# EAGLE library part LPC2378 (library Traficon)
LPC2378 Single-chip 16-bit/32-bit microcontrollers; 512 kB flash with ISP/IAP, Ethernet, USB 2.0, CAN, 10-bit ADC/DAC
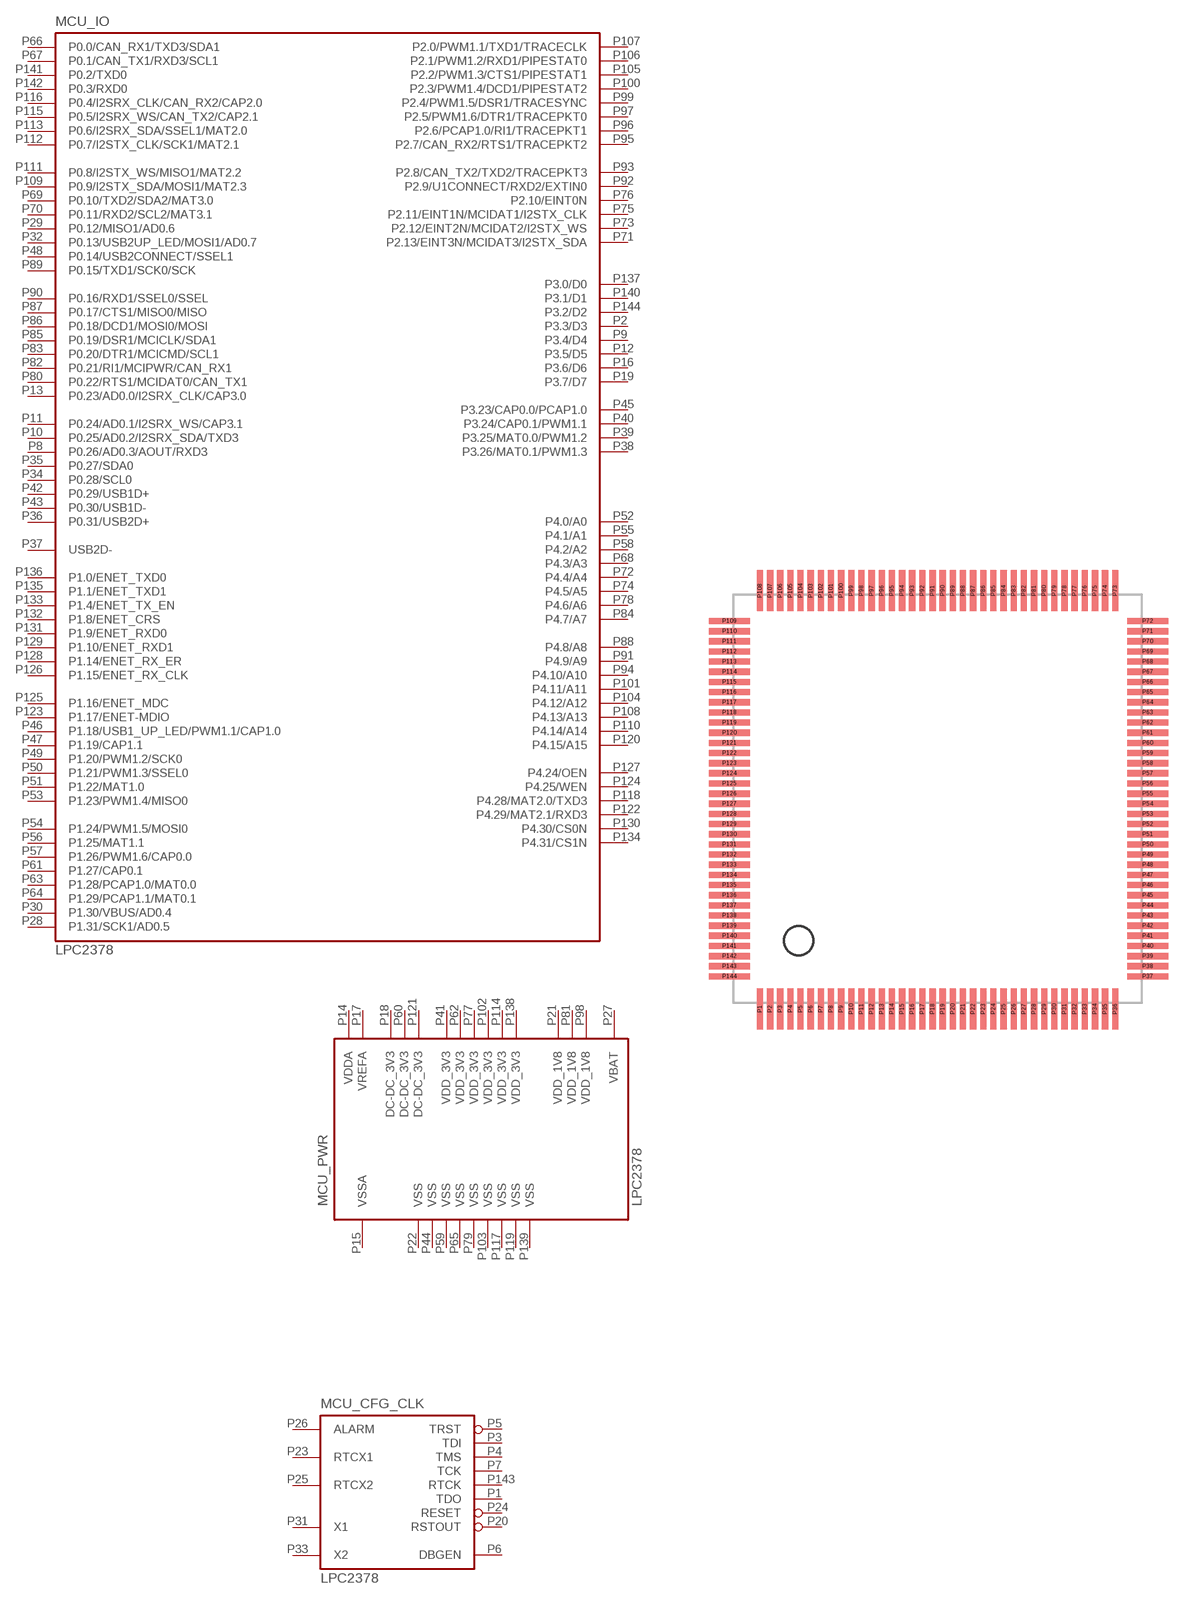
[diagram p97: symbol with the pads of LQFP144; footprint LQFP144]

Designator prefix MCU; gates _IO=LPC2378_IO _CFG_CLK=LPC_2378_MISC _PWR=LPC2378_POWER

## LPC2378FPD144  [LQFP144]
P1  _CFG_CLK:TDO
P2  _IO:P3.3/D3
P3  _CFG_CLK:TDI
P4  _CFG_CLK:TMS
P5  _CFG_CLK:TRST
P6  _CFG_CLK:DBGEN
P7  _CFG_CLK:TCK
P8  _IO:P0.26/AD0.3/AOUT/RXD3
P9  _IO:P3.4/D4
P10  _IO:P0.25/AD0.2/I2SRX_SDA/TXD3
P11  _IO:P0.24/AD0.1/I2SRX_WS/CAP3.1
P12  _IO:P3.5/D5
P13  _IO:P0.23/AD0.0/I2SRX_CLK/CAP3.0
P14  _PWR:VDDA  pwr
P15  _PWR:VSSA  pwr
P16  _IO:P3.6/D6
P17  _PWR:VREFA  pwr
P18  _PWR:DC-DC_3V3  pas
P19  _IO:P3.7/D7
P20  _CFG_CLK:RSTOUT
P21  _PWR:VDD_1V8  pwr
P22  _PWR:VSS  pwr
P23  _CFG_CLK:RTCX1
P24  _CFG_CLK:RESET
P25  _CFG_CLK:RTCX2
P26  _CFG_CLK:ALARM
P27  _PWR:VBAT  pwr
P28  _IO:P1.31/SCK1/AD0.5
P29  _IO:P0.12/MISO1/AD0.6
P30  _IO:P1.30/VBUS/AD0.4
P31  _CFG_CLK:X1
P32  _IO:P0.13/USB2UP_LED/MOSI1/AD0.7
P33  _CFG_CLK:X2
P34  _IO:P0.28/SCL0
P35  _IO:P0.27/SDA0
P36  _IO:P0.31/USB2D+
P37  _IO:USB2D-
P38  _IO:P3.26/MAT0.1/PWM1.3
P39  _IO:P3.25/MAT0.0/PWM1.2
P40  _IO:P3.24/CAP0.1/PWM1.1
P41  _PWR:VDD_3V3  pwr
P42  _IO:P0.29/USB1D+
P43  _IO:P0.30/USB1D-
P44  _PWR:VSS  pwr
P45  _IO:P3.23/CAP0.0/PCAP1.0
P46  _IO:P1.18/USB1_UP_LED/PWM1.1/CAP1.0
P47  _IO:P1.19/CAP1.1
P48  _IO:P0.14/USB2CONNECT/SSEL1
P49  _IO:P1.20/PWM1.2/SCK0
P50  _IO:P1.21/PWM1.3/SSEL0
P51  _IO:P1.22/MAT1.0
P52  _IO:P4.0/A0
P53  _IO:P1.23/PWM1.4/MISO0
P54  _IO:P1.24/PWM1.5/MOSI0
P55  _IO:P4.1/A1
P56  _IO:P1.25/MAT1.1
P57  _IO:P1.26/PWM1.6/CAP0.0
P58  _IO:P4.2/A2
P59  _PWR:VSS  pwr
P60  _PWR:DC-DC_3V3  pas
P61  _IO:P1.27/CAP0.1
P62  _PWR:VDD_3V3  pwr
P63  _IO:P1.28/PCAP1.0/MAT0.0
P64  _IO:P1.29/PCAP1.1/MAT0.1
P65  _PWR:VSS  pwr
P66  _IO:P0.0/CAN_RX1/TXD3/SDA1
P67  _IO:P0.1/CAN_TX1/RXD3/SCL1
P68  _IO:P4.3/A3
P69  _IO:P0.10/TXD2/SDA2/MAT3.0
P70  _IO:P0.11/RXD2/SCL2/MAT3.1
P71  _IO:P2.13/EINT3N/MCIDAT3/I2STX_SDA
P72  _IO:P4.4/A4
P73  _IO:P2.12/EINT2N/MCIDAT2/I2STX_WS
P74  _IO:P4.5/A5
P75  _IO:P2.11/EINT1N/MCIDAT1/I2STX_CLK
P76  _IO:P2.10/EINT0N
P77  _PWR:VDD_3V3  pwr
P78  _IO:P4.6/A6
P79  _PWR:VSS  pwr
P80  _IO:P0.22/RTS1/MCIDAT0/CAN_TX1
P81  _PWR:VDD_1V8  pwr
P82  _IO:P0.21/RI1/MCIPWR/CAN_RX1
P83  _IO:P0.20/DTR1/MCICMD/SCL1
P84  _IO:P4.7/A7
P85  _IO:P0.19/DSR1/MCICLK/SDA1
P86  _IO:P0.18/DCD1/MOSI0/MOSI
P87  _IO:P0.17/CTS1/MISO0/MISO
P88  _IO:P4.8/A8
P89  _IO:P0.15/TXD1/SCK0/SCK
P90  _IO:P0.16/RXD1/SSEL0/SSEL
P91  _IO:P4.9/A9
P92  _IO:P2.9/U1CONNECT/RXD2/EXTIN0
P93  _IO:P2.8/CAN_TX2/TXD2/TRACEPKT3
P94  _IO:P4.10/A10
P95  _IO:P2.7/CAN_RX2/RTS1/TRACEPKT2
P96  _IO:P2.6/PCAP1.0/RI1/TRACEPKT1
P97  _IO:P2.5/PWM1.6/DTR1/TRACEPKT0
P98  _PWR:VDD_1V8  pwr
P99  _IO:P2.4/PWM1.5/DSR1/TRACESYNC
P100  _IO:P2.3/PWM1.4/DCD1/PIPESTAT2
P101  _IO:P4.11/A11
P102  _PWR:VDD_3V3  pwr
P103  _PWR:VSS  pwr
P104  _IO:P4.12/A12
P105  _IO:P2.2/PWM1.3/CTS1/PIPESTAT1
P106  _IO:P2.1/PWM1.2/RXD1/PIPESTAT0
P107  _IO:P2.0/PWM1.1/TXD1/TRACECLK
P108  _IO:P4.13/A13
P109  _IO:P0.9/I2STX_SDA/MOSI1/MAT2.3
P110  _IO:P4.14/A14
P111  _IO:P0.8/I2STX_WS/MISO1/MAT2.2
P112  _IO:P0.7/I2STX_CLK/SCK1/MAT2.1
P113  _IO:P0.6/I2SRX_SDA/SSEL1/MAT2.0
P114  _PWR:VDD_3V3  pwr
P115  _IO:P0.5/I2SRX_WS/CAN_TX2/CAP2.1
P116  _IO:P0.4/I2SRX_CLK/CAN_RX2/CAP2.0
P117  _PWR:VSS  pwr
P118  _IO:P4.28/MAT2.0/TXD3
P119  _PWR:VSS  pwr
P120  _IO:P4.15/A15
P121  _PWR:DC-DC_3V3  pas
P122  _IO:P4.29/MAT2.1/RXD3
P123  _IO:P1.17/ENET-MDIO
P124  _IO:P4.25/WEN
P125  _IO:P1.16/ENET_MDC
P126  _IO:P1.15/ENET_RX_CLK
P127  _IO:P4.24/OEN
P128  _IO:P1.14/ENET_RX_ER
P129  _IO:P1.10/ENET_RXD1
P130  _IO:P4.30/CS0N
P131  _IO:P1.9/ENET_RXD0
P132  _IO:P1.8/ENET_CRS
P133  _IO:P1.4/ENET_TX_EN
P134  _IO:P4.31/CS1N
P135  _IO:P1.1/ENET_TXD1
P136  _IO:P1.0/ENET_TXD0
P137  _IO:P3.0/D0
P138  _PWR:VDD_3V3  pwr
P139  _PWR:VSS  pwr
P140  _IO:P3.1/D1
P141  _IO:P0.2/TXD0
P142  _IO:P0.3/RXD0
P143  _CFG_CLK:RTCK
P144  _IO:P3.2/D2

## Footprint LQFP144 (pad centres in mm)
smd 0.305 x 2: P1 -8.89,-10.34; P2 -8.39,-10.34; P3 -7.89,-10.34; P4 -7.39,-10.34; P5 -6.89,-10.34; P6 -6.39,-10.34; P7 -5.89,-10.34; P8 -5.39,-10.34; P9 -4.89,-10.34; P10 -4.39,-10.34; P11 -3.89,-10.34; P12 -3.39,-10.34; P13 -2.89,-10.34; P14 -2.39,-10.34; P15 -1.89,-10.34; P16 -1.39,-10.34; P17 -0.89,-10.34; P18 -0.39,-10.34; P19 0.11,-10.34; P20 0.61,-10.34; P21 1.11,-10.34; P22 1.61,-10.34; P23 2.11,-10.34; P24 2.61,-10.34; P25 3.11,-10.34; P26 3.61,-10.34; P27 4.11,-10.34; P28 4.61,-10.34; P29 5.11,-10.34; P30 5.61,-10.34; P31 6.11,-10.34; P32 6.61,-10.34; P33 7.11,-10.34; P34 7.61,-10.34; P35 8.11,-10.34; P36 8.61,-10.34; P73 8.61,10.26; P74 8.11,10.26; P75 7.61,10.26; P76 7.11,10.26; P77 6.61,10.26; P78 6.11,10.26; P79 5.61,10.26; P80 5.11,10.26; P81 4.61,10.26; P82 4.11,10.26; P83 3.61,10.26; P84 3.11,10.26; P85 2.61,10.26; P86 2.11,10.26; P87 1.61,10.26; P88 1.11,10.26; P89 0.61,10.26; P90 0.11,10.26; P91 -0.39,10.26; P92 -0.89,10.26; P93 -1.39,10.26; P94 -1.89,10.26; P95 -2.39,10.26; P96 -2.89,10.26; P97 -3.39,10.26; P98 -3.89,10.26; P99 -4.39,10.26; P100 -4.89,10.26; P101 -5.39,10.26; P102 -5.89,10.26; P103 -6.39,10.26; P104 -6.89,10.26; P105 -7.39,10.26; P106 -7.89,10.26; P107 -8.39,10.26; P108 -8.89,10.26
smd 2 x 0.305: P37 10.21,-8.74; P38 10.21,-8.24; P39 10.21,-7.74; P40 10.21,-7.24; P41 10.21,-6.74; P42 10.21,-6.24; P43 10.21,-5.74; P44 10.21,-5.24; P45 10.21,-4.74; P46 10.21,-4.24; P47 10.21,-3.74; P48 10.21,-3.24; P49 10.21,-2.74; P50 10.21,-2.24; P51 10.21,-1.74; P52 10.21,-1.24; P53 10.21,-0.74; P54 10.21,-0.24; P55 10.21,0.26; P56 10.21,0.76; P57 10.21,1.26; P58 10.21,1.76; P59 10.21,2.26; P60 10.21,2.76; P61 10.21,3.26; P62 10.21,3.76; P63 10.21,4.26; P64 10.21,4.76; P65 10.21,5.26; P66 10.21,5.76; P67 10.21,6.26; P68 10.21,6.76; P69 10.21,7.26; P70 10.21,7.76; P71 10.21,8.26; P72 10.21,8.76; P109 -10.39,8.76; P110 -10.39,8.26; P111 -10.39,7.76; P112 -10.39,7.26; P113 -10.39,6.76; P114 -10.39,6.26; P115 -10.39,5.76; P116 -10.39,5.26; P117 -10.39,4.76; P118 -10.39,4.26; P119 -10.39,3.76; P120 -10.39,3.26; P121 -10.39,2.76; P122 -10.39,2.26; P123 -10.39,1.76; P124 -10.39,1.26; P125 -10.39,0.76; P126 -10.39,0.26; P127 -10.39,-0.24; P128 -10.39,-0.74; P129 -10.39,-1.24; P130 -10.39,-1.74; P131 -10.39,-2.24; P132 -10.39,-2.74; P133 -10.39,-3.24; P134 -10.39,-3.74; P135 -10.39,-4.24; P136 -10.39,-4.74; P137 -10.39,-5.24; P138 -10.39,-5.74; P139 -10.39,-6.24; P140 -10.39,-6.74; P141 -10.39,-7.24; P142 -10.39,-7.74; P143 -10.39,-8.24; P144 -10.39,-8.74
